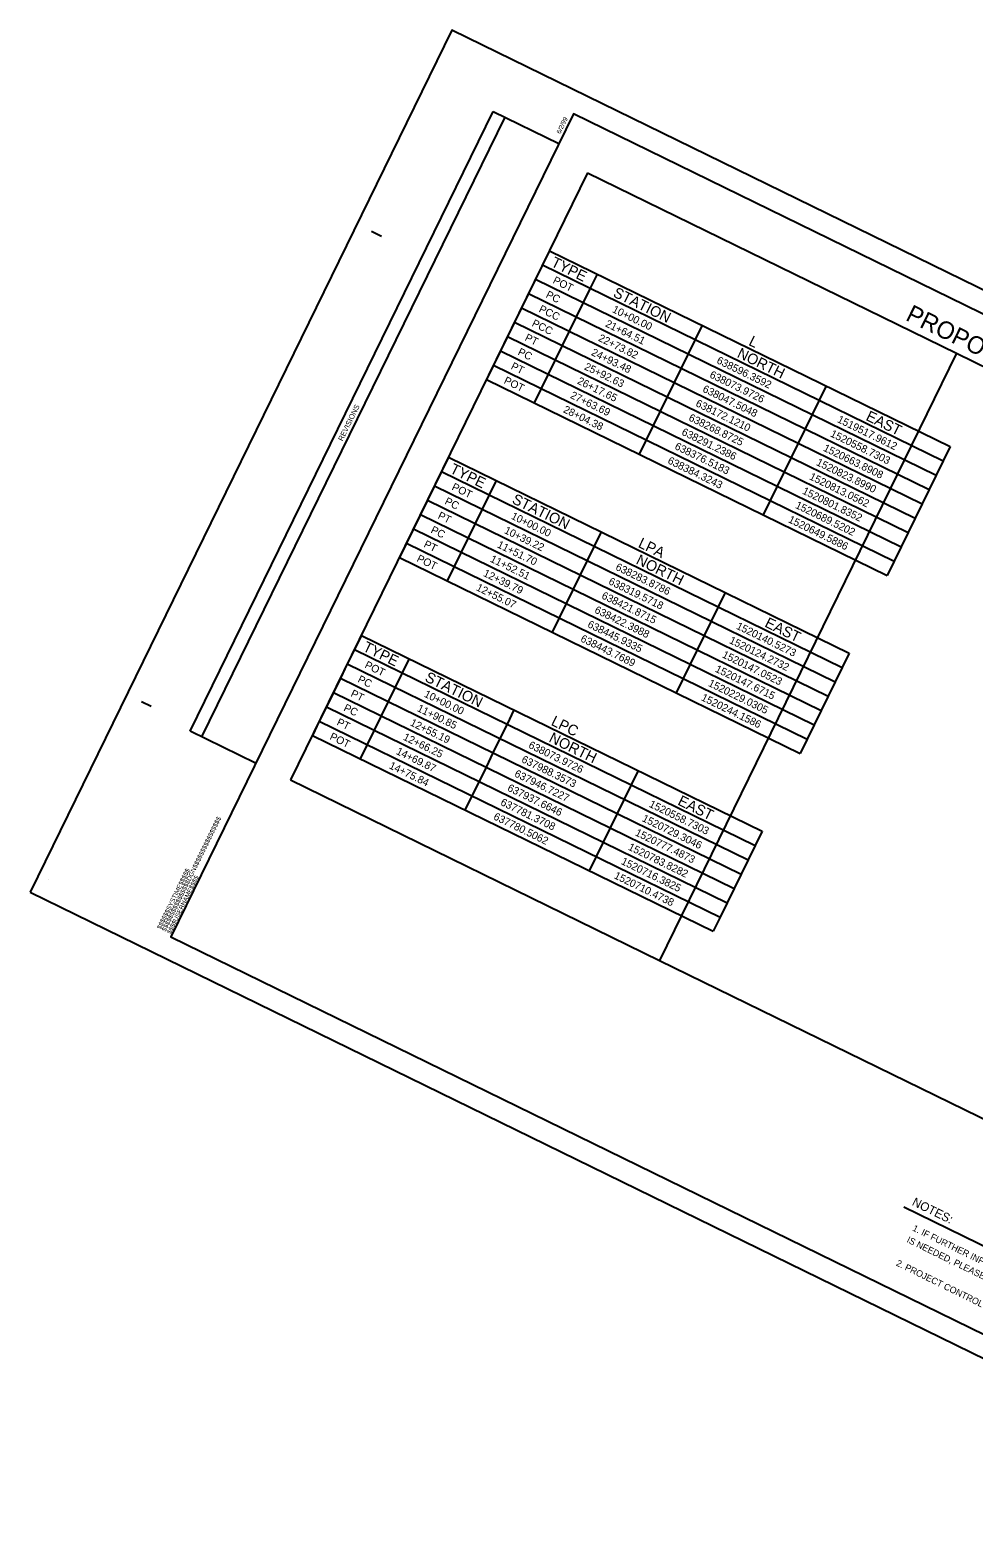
# Model space of a CAD drawing. Extents: x 1523259 to 1525268, y 635471 to 637211.
# Drawn here: x 1523259 to 1524347, y 635471 to 637211 of the extents above; entities that cross this region are included whole.
import ezdxf

# ---------------------------------------------------------------- set-up
doc = ezdxf.new("R2010")
doc.units = 0
for name, color, linetype in [('CTL Sheet Border CELL', 7, 'Continuous'), ('CTL Sheet Notes CELL', 7, 'Continuous'), ('CTL Sheet Table Cell', 7, 'Continuous'), ('CTL Sheet Text', 7, 'Continuous'), ('Scratch_Level_3', 7, 'Continuous'), ('Sheet Block Revision CELL', 7, 'Continuous'), ('Sheet Plot Border Outside CELL', 7, 'Continuous')]:
    doc.layers.add(name, color=color, linetype=linetype)

msp = doc.modelspace()

# ---------------------------------------------------------------- linework, layer by layer
at = {"layer": 'CTL Sheet Border CELL'}
for p, q in [((1523652.5, 636978.8), (1523663.8, 636973.3)), ((1523387.1, 636436.3), (1523398.4, 636430.7)), ((1523258.7, 636216.1), (1523258.7, 636216.1)), ((1523280.4, 636230.7), (1523280.4, 636230.7)), ((1523420.8, 636164.9), (1523420.8, 636164.9)), ((1523420.8, 636164.9), (1523420.8, 636164.9)), ((1523420.8, 636164.9), (1523420.8, 636164.9)), ((1523420.8, 636164.9), (1523420.8, 636164.9)), ((1523420.8, 636164.9), (1523420.8, 636164.9)), ((1523420.8, 636164.9), (1523420.8, 636164.9)), ((1523420.8, 636164.9), (1523420.8, 636164.9)), ((1523420.8, 636164.9), (1523420.8, 636164.9)), ((1523420.8, 636164.9), (1523420.8, 636164.9)), ((1523420.8, 636164.9), (1523420.8, 636164.9)), ((1523420.8, 636164.9), (1523420.8, 636164.9))]:
    msp.add_line(p, q, dxfattribs=at)
msp.add_lwpolyline([(1525241.6, 636451), (1523885.2, 637114.4), (1523420.8, 636164.9), (1524777.2, 635501.4)], close=True, dxfattribs=at)
msp.add_lwpolyline([(1523454.7, 636148.3), (1523454.7, 636148.3)], dxfattribs=at)
msp.add_lwpolyline([(1523454.7, 636148.3), (1523454.7, 636148.3)], dxfattribs=at)
at = {"layer": 'CTL Sheet Notes CELL'}
msp.add_line((1524266.2, 635853.1), (1524743.2, 635619.8), dxfattribs=at)
at = {"layer": 'CTL Sheet Table Cell'}
for p, q in [((1523857.7, 636956.4), (1523849.6, 636939.9)), ((1523857.7, 636956.4), (1524319.9, 636730.4)), ((1523849.6, 636939.9), (1523841.6, 636923.4)), ((1523849.6, 636939.9), (1524311.8, 636713.9)), ((1523912.7, 636929.5), (1523904.7, 636913)), ((1523841.6, 636923.4), (1523833.5, 636906.9)), ((1523841.6, 636923.4), (1524303.8, 636697.4)), ((1523904.7, 636913), (1523896.6, 636896.5)), ((1523833.5, 636906.9), (1523825.4, 636890.4)), ((1523833.5, 636906.9), (1524295.7, 636680.8)), ((1523896.6, 636896.5), (1523888.5, 636880)), ((1523825.4, 636890.4), (1523817.3, 636873.9)), ((1523825.4, 636890.4), (1524287.6, 636664.3)), ((1523888.5, 636880), (1523880.4, 636863.5)), ((1523817.3, 636873.9), (1523809.3, 636857.4)), ((1523817.3, 636873.9), (1524279.5, 636647.8)), ((1523880.4, 636863.5), (1523872.4, 636847)), ((1524033.8, 636870.3), (1524025.7, 636853.8)), ((1523809.3, 636857.4), (1523801.2, 636840.9)), ((1523809.3, 636857.4), (1524271.5, 636631.3)), ((1523872.4, 636847), (1523864.3, 636830.5)), ((1524025.7, 636853.8), (1524017.6, 636837.3)), ((1523793.1, 636824.4), (1523785.1, 636807.9)), ((1523801.2, 636840.9), (1523793.1, 636824.4)), ((1523793.1, 636824.4), (1524255.3, 636598.3)), ((1523801.2, 636840.9), (1524263.4, 636614.8)), ((1523864.3, 636830.5), (1523856.2, 636814)), ((1524017.6, 636837.3), (1524009.6, 636820.8)), ((1523785.1, 636807.9), (1524247.2, 636581.8)), ((1523856.2, 636814), (1523848.2, 636797.4)), ((1524009.6, 636820.8), (1524001.5, 636804.3)), ((1523848.2, 636797.4), (1523840.1, 636780.9)), ((1524001.5, 636804.3), (1523993.4, 636787.8)), ((1524176.8, 636800.3), (1524168.8, 636783.8)), ((1523993.4, 636787.8), (1523985.3, 636771.3)), ((1524168.8, 636783.8), (1524160.7, 636767.3)), ((1523977.3, 636754.8), (1523969.2, 636738.2)), ((1523985.3, 636771.3), (1523977.3, 636754.8)), ((1524160.7, 636767.3), (1524152.6, 636750.8)), ((1523969.2, 636738.2), (1523961.1, 636721.7)), ((1524152.6, 636750.8), (1524144.5, 636734.3)), ((1524144.5, 636734.3), (1524136.5, 636717.8)), ((1524319.9, 636730.4), (1524311.8, 636713.9)), ((1523741.1, 636718), (1523733, 636701.5)), ((1523741.1, 636718), (1524203.3, 636492)), ((1524136.5, 636717.8), (1524128.4, 636701.3)), ((1524311.8, 636713.9), (1524303.8, 636697.4)), ((1523733, 636701.5), (1523725, 636685)), ((1523733, 636701.5), (1524195.2, 636475.5)), ((1523796.1, 636691.1), (1523788.1, 636674.6)), ((1524128.4, 636701.3), (1524120.3, 636684.8)), ((1524303.8, 636697.4), (1524295.7, 636680.8)), ((1523716.9, 636668.5), (1523708.8, 636652)), ((1523725, 636685), (1523716.9, 636668.5)), ((1523716.9, 636668.5), (1524179.1, 636442.5)), ((1523725, 636685), (1524187.2, 636459)), ((1523788.1, 636674.6), (1523780, 636658.1)), ((1524112.3, 636668.3), (1524104.2, 636651.8)), ((1524120.3, 636684.8), (1524112.3, 636668.3)), ((1524295.7, 636680.8), (1524287.6, 636664.3)), ((1523708.8, 636652), (1523700.8, 636635.5)), ((1523708.8, 636652), (1524171, 636425.9)), ((1523780, 636658.1), (1523771.9, 636641.6)), ((1524287.6, 636664.3), (1524279.5, 636647.8)), ((1523700.8, 636635.5), (1523692.7, 636619)), ((1523700.8, 636635.5), (1524162.9, 636409.4)), ((1523771.9, 636641.6), (1523763.9, 636625.1)), ((1524279.5, 636647.8), (1524271.5, 636631.3)), ((1523692.7, 636619), (1523684.6, 636602.5)), ((1523692.7, 636619), (1524154.9, 636392.9)), ((1523763.9, 636625.1), (1523755.8, 636608.6)), ((1523917.2, 636631.9), (1523909.1, 636615.4)), ((1524271.5, 636631.3), (1524263.4, 636614.8)), ((1523684.6, 636602.5), (1524146.8, 636376.4)), ((1523755.8, 636608.6), (1523747.7, 636592.1)), ((1523901, 636598.9), (1523893, 636582.4)), ((1523909.1, 636615.4), (1523901, 636598.9)), ((1524255.3, 636598.3), (1524247.2, 636581.8)), ((1524263.4, 636614.8), (1524255.3, 636598.3)), ((1523747.7, 636592.1), (1523739.6, 636575.6)), ((1523893, 636582.4), (1523884.9, 636565.9)), ((1523884.9, 636565.9), (1523876.8, 636549.4)), ((1523876.8, 636549.4), (1523868.8, 636532.9)), ((1524060.2, 636561.9), (1524052.2, 636545.4)), ((1523868.8, 636532.9), (1523860.7, 636516.4)), ((1524044.1, 636528.9), (1524036, 636512.4)), ((1524052.2, 636545.4), (1524044.1, 636528.9)), ((1523640.7, 636512.6), (1523632.6, 636496.1)), ((1523640.7, 636512.6), (1524102.9, 636286.6)), ((1524036, 636512.4), (1524028, 636495.9)), ((1523632.6, 636496.1), (1523624.5, 636479.6)), ((1523632.6, 636496.1), (1524094.8, 636270.1)), ((1524028, 636495.9), (1524019.9, 636479.4)), ((1523624.5, 636479.6), (1523616.5, 636463.1)), ((1523624.5, 636479.6), (1524086.7, 636253.6)), ((1523695.7, 636485.7), (1523687.6, 636469.2)), ((1524019.9, 636479.4), (1524011.8, 636462.9)), ((1524203.3, 636492), (1524195.2, 636475.5)), ((1523616.5, 636463.1), (1523608.4, 636446.6)), ((1523616.5, 636463.1), (1524078.6, 636237.1)), ((1523687.6, 636469.2), (1523679.6, 636452.7)), ((1524011.8, 636462.9), (1524003.7, 636446.4)), ((1524195.2, 636475.5), (1524187.2, 636459)), ((1523608.4, 636446.6), (1523600.3, 636430.1)), ((1523608.4, 636446.6), (1524070.6, 636220.6)), ((1523679.6, 636452.7), (1523671.5, 636436.2)), ((1524179.1, 636442.5), (1524171, 636425.9)), ((1524187.2, 636459), (1524179.1, 636442.5)), ((1523600.3, 636430.1), (1523592.2, 636413.6)), ((1523600.3, 636430.1), (1524062.5, 636204.1)), ((1523671.5, 636436.2), (1523663.4, 636419.7)), ((1523816.7, 636426.5), (1523808.7, 636410)), ((1524171, 636425.9), (1524162.9, 636409.4)), ((1523592.2, 636413.6), (1523584.2, 636397.1)), ((1523592.2, 636413.6), (1524054.4, 636187.6)), ((1523663.4, 636419.7), (1523655.3, 636403.2)), ((1523808.7, 636410), (1523800.6, 636393.5)), ((1524162.9, 636409.4), (1524154.9, 636392.9)), ((1523584.2, 636397.1), (1524046.3, 636171.1)), ((1523655.3, 636403.2), (1523647.3, 636386.7)), ((1523800.6, 636393.5), (1523792.5, 636377)), ((1524154.9, 636392.9), (1524146.8, 636376.4)), ((1523647.3, 636386.7), (1523639.2, 636370.2)), ((1523792.5, 636377), (1523784.5, 636360.5)), ((1523784.5, 636360.5), (1523776.4, 636344)), ((1523959.8, 636356.6), (1523951.7, 636340.1)), ((1523776.4, 636344), (1523768.3, 636327.5)), ((1523951.7, 636340.1), (1523943.7, 636323.6)), ((1523768.3, 636327.5), (1523760.2, 636311)), ((1523943.7, 636323.6), (1523935.6, 636307)), ((1523935.6, 636307), (1523927.5, 636290.5)), ((1523927.5, 636290.5), (1523919.4, 636274)), ((1524102.9, 636286.6), (1524094.8, 636270.1)), ((1523919.4, 636274), (1523911.4, 636257.5)), ((1524094.8, 636270.1), (1524086.7, 636253.6)), ((1523911.4, 636257.5), (1523903.3, 636241)), ((1524086.7, 636253.6), (1524078.6, 636237.1)), ((1524078.6, 636237.1), (1524070.6, 636220.6)), ((1524070.6, 636220.6), (1524062.5, 636204.1)), ((1524062.5, 636204.1), (1524054.4, 636187.6)), ((1524054.4, 636187.6), (1524046.3, 636171.1))]:
    msp.add_line(p, q, dxfattribs=at)
at = {"layer": 'Scratch_Level_3'}
for p, q in [((1523901.6, 637046.2), (1523559, 636345.7)), ((1523901.6, 637046.2), (1524327, 636838.2)), ((1524327, 636838.2), (1523984.4, 636137.6)), ((1524327, 636838.2), (1524752.4, 636630.2)), ((1523559, 636345.7), (1523984.4, 636137.6)), ((1523984.4, 636137.6), (1524409.7, 635929.6))]:
    msp.add_line(p, q, dxfattribs=at)
at = {"layer": 'Sheet Block Revision CELL'}
for p, q in [((1523443.2, 636402.1), (1523792.8, 637116.9)), ((1523456.8, 636395.5), (1523806.4, 637110.3)), ((1523792.8, 637116.9), (1523868.3, 637080)), ((1523518.7, 636365.2), (1523443.2, 636402.1))]:
    msp.add_line(p, q, dxfattribs=at)
at = {"layer": 'Sheet Plot Border Outside CELL'}
msp.add_lwpolyline([(1523258.7, 636216.1), (1524781.6, 635471.3), (1525268.1, 636466), (1523745.2, 637210.8)], close=True, dxfattribs=at)

# ---------------------------------------------------------------- texts
at = {"layer": 'CTL Sheet Border CELL'}
for s, height, rotation, p in [('6/2/99', 5.29, 63.9377, (1523870.1, 637090.7)), ('PROPOSED ALIGNMENT CONTROL SHEET', 20.133, 333.9377, (1524267.3, 636876.7)), ('$$$$$$$$$$$$$$$$DGN$$$$$$$$$$$$$$$$', 5.285, 63.9377, (1523414.9, 636170.4)), ('$$$$$$SYSTIME$$$$$', 5.285, 63.9377, (1523409.4, 636173)), ('$$$$USERNAME$$$$', 5.285, 63.9377, (1523420.9, 636167.5))]:
    msp.add_text(s, height=height, rotation=rotation, dxfattribs=at).set_placement(p)
at = {"layer": 'CTL Sheet Notes CELL'}
for s, height, rotation, p in [('TYPE', 12.25, 333.9377, (1523858.5, 636939)), ('STATION', 12.25, 333.9377, (1523930.1, 636903.9)), ('NORTH', 12.25, 333.9377, (1524073.1, 636834)), ('L', 12.3, 333.9377, (1524086.5, 636847.9)), ('EAST', 12.25, 333.9377, (1524221.6, 636761.4)), ('TYPE', 12.25, 333.9377, (1523741.9, 636700.6)), ('STATION', 12.25, 333.9377, (1523813.5, 636665.6)), ('LPA', 12.25, 333.9377, (1523959, 636614.9)), ('NORTH', 12.25, 333.9377, (1523956.5, 636595.6)), ('EAST', 12.25, 333.9377, (1524105, 636523)), ('TYPE', 12.25, 333.9377, (1523641.4, 636495.2)), ('STATION', 12.25, 333.9377, (1523713.1, 636460.2)), ('LPC', 12.25, 333.9377, (1523858.6, 636409.5)), ('NORTH', 12.25, 333.9377, (1523856.1, 636390.3)), ('EAST', 12.25, 333.9377, (1524004.6, 636317.6)), ('NOTES:', 10.07, 333.8325, (1524275, 635855.5)), ('IS NEEDED, PLEASE CONTACT THE LOCATION AND SURVEYS UNIT.', 7.55, 333.9377, (1524269, 635812.7)), ('1. IF FURTHER INFORMATION REGARDING PROJECT CONTROL', 7.55, 333.9377, (1524275.6, 635826.1)), ('2. PROJECT CONTROL WAS ESTABLISHED USING GNSS,  THE GLOBAL NAVIGATION SATELLITE SYSTEM.', 7.548, 333.8325, (1524256.7, 635785.8))]:
    msp.add_text(s, height=height, rotation=rotation, dxfattribs=at).set_placement(p)
at = {"layer": 'CTL Sheet Text'}
for s, p in [('POT', (1523860.8, 636919.4)), ('PC ', (1523852.7, 636902.8)), ('PCC', (1523836.6, 636869.8)), ('PCC', (1523844.7, 636886.3)), ('10+00.00', (1523929.3, 636885.8)), ('PT ', (1523828.5, 636853.3)), ('22+73.82', (1523913.2, 636852.8)), ('21+64.51', (1523921.3, 636869.3)), ('PC ', (1523820.4, 636836.8)), ('24+93.48', (1523905.1, 636836.3)), ('PT ', (1523812.4, 636820.3)), ('25+92.63', (1523897, 636819.8)), ('638596.3592', (1524049.7, 636827)), ('POT', (1523804.3, 636803.8)), ('26+17.65', (1523889, 636803.3)), ('638073.9726', (1524041.6, 636810.5)), ('27+63.69', (1523880.9, 636786.8)), ('638047.5048', (1524033.5, 636794)), ('28+04.38', (1523872.8, 636770.3)), ('638172.1210', (1524025.5, 636777.4)), ('638268.8725', (1524017.4, 636760.9)), ('1519517.9612', (1524188.8, 636758.9)), ('638291.2386', (1524009.3, 636744.4)), ('1520558.7303', (1524180.8, 636742.4)), ('638376.5183', (1524001.3, 636727.9)), ('1520663.8908', (1524172.7, 636725.9)), ('638384.3243', (1523993.2, 636711.4)), ('1520823.8990', (1524164.6, 636709.4)), ('POT', (1523744.2, 636681)), ('1520813.0562', (1524156.6, 636692.9)), ('PC ', (1523736.1, 636664.5)), ('1520801.8352', (1524148.5, 636676.4)), ('PT ', (1523728.1, 636647.9)), ('10+00.00', (1523812.7, 636647.4)), ('1520689.5202', (1524140.4, 636659.9)), ('PC ', (1523720, 636631.4)), ('10+39.22', (1523804.7, 636630.9)), ('1520649.5886', (1524132.3, 636643.4)), ('PT ', (1523711.9, 636614.9)), ('11+51.70', (1523796.6, 636614.4)), ('POT', (1523703.8, 636598.4)), ('11+52.51', (1523788.5, 636597.9)), ('12+39.79', (1523780.5, 636581.4)), ('638283.8786', (1523933.1, 636588.6)), ('12+55.07', (1523772.4, 636564.9)), ('638319.5718', (1523925, 636572.1)), ('638422.3988', (1523908.9, 636539.1)), ('638421.8715', (1523917, 636555.6)), ('638445.9335', (1523900.8, 636522.5)), ('638443.7689', (1523892.7, 636506)), ('1520140.5273', (1524072.3, 636520.5)), ('1520147.0523', (1524056.1, 636487.5)), ('1520124.2732', (1524064.2, 636504)), ('POT', (1523643.8, 636475.6)), ('1520147.6715', (1524048, 636471)), ('PC ', (1523635.7, 636459.1)), ('1520229.0305', (1524040, 636454.5)), ('PT ', (1523627.6, 636442.6)), ('10+00.00', (1523712.3, 636442.1)), ('1520244.1586', (1524031.9, 636438)), ('PC ', (1523619.5, 636426.1)), ('11+90.85', (1523704.2, 636425.6)), ('PT ', (1523611.5, 636409.6)), ('12+55.19', (1523696.2, 636409)), ('POT', (1523603.4, 636393)), ('12+66.25', (1523688.1, 636392.5)), ('638073.9726', (1523832.7, 636383.2)), ('14+69.87', (1523680, 636376)), ('637988.3573', (1523824.6, 636366.7)), ('14+75.84', (1523671.9, 636359.5)), ('637946.7227', (1523816.5, 636350.2)), ('637937.6646', (1523808.4, 636333.7)), ('637781.3708', (1523800.4, 636317.2)), ('1520558.7303', (1523971.8, 636315.1)), ('637780.5062', (1523792.3, 636300.7)), ('1520729.3046', (1523963.7, 636298.6)), ('1520777.4873', (1523955.7, 636282.1)), ('1520783.8282', (1523947.6, 636265.6)), ('1520716.3825', (1523939.5, 636249.1)), ('1520710.4738', (1523931.4, 636232.6))]:
    msp.add_text(s, height=8.75, rotation=333.9377, dxfattribs=at).set_placement(p)
at = {"layer": 'Sheet Block Revision CELL'}
msp.add_text('REVISIONS', height=6.04, rotation=63.9377, dxfattribs=at).set_placement((1523619, 636736.2))

doc.saveas('drawing.dxf')
